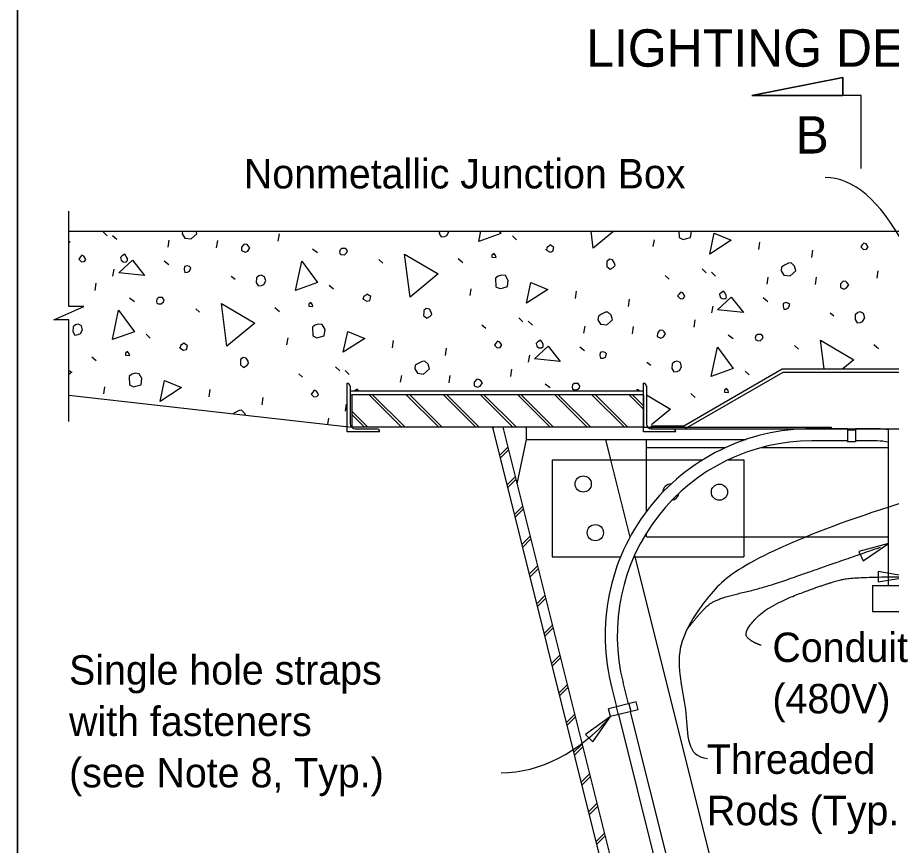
# Model space of a CAD drawing. Extents: x 0 to 30.8, y 0 to 21.2.
# Drawn here: x 0 to 4.493, y 5.377 to 9.634 of the extents above; entities that cross this region are included whole.
import ezdxf

# ---------------------------------------------------------------- set-up
doc = ezdxf.new("R2010")
doc.units = 0
for name, color, linetype in [('ActivePts-ConstElements', 7, 'Continuous'), ('Dimension', 7, 'Continuous'), ('Lighting', 7, 'Continuous'), ('Miscellaneous', 7, 'Continuous'), ('Miscellaneous1', 7, 'Continuous'), ('SteelGirder', 7, 'Continuous'), ('SteelGirder_h', 7, 'Continuous'), ('SupstrConc', 7, 'Continuous'), ('TextStructures', 7, 'Continuous')]:
    doc.layers.add(name, color=color, linetype=linetype)

msp = doc.modelspace()

# ---------------------------------------------------------------- linework, layer by layer
at = {"layer": 'ActivePts-ConstElements'}
msp.add_lwpolyline([(0, 0), (30.7879, 0), (30.7879, 19.4596), (0, 19.4596)], close=True, dxfattribs=at)
at = {"layer": 'Dimension'}
for p, q in [((3.7747, 9.2323), (4.2434, 9.3261)), ((4.2434, 9.3261), (4.2434, 9.2323)), ((4.3372, 9.2323), (3.7747, 9.2323)), ((4.3372, 8.8573), (4.3372, 9.2323))]:
    msp.add_line(p, q, dxfattribs=at)
for points in [[(4.2434, 9.2323), (4.2434, 9.3261), (3.7747, 9.2323)], [(4.4782, 6.9304), (4.3252, 6.8892), (4.3473, 6.8412)], [(4.5805, 6.7589), (4.4243, 6.7853), (4.4243, 6.7324)], [(3.0493, 6.0401), (2.92, 5.9486), (2.9574, 5.9111)]]:
    msp.add_lwpolyline(points, close=True, dxfattribs=at)
msp.add_lwpolyline([(0.2637, 7.5579), (0.2637, 8.0801), (0.1862, 8.0801), (0.2637, 8.1139), (0.3412, 8.1476), (0.2637, 8.1476), (0.2637, 8.638)], dxfattribs=at)
for centre, major_axis, ratio, start_param, end_param in [((4.1852, 6.2941), (0.0332, -2.5173), 0.313255, 2.075166, 3.141607), ((2.472, 7.3449), (-0.0144, 1.5941), 0.622544, 3.141613, 3.747853)]:
    msp.add_ellipse(centre, major_axis=major_axis, ratio=ratio, start_param=start_param, end_param=end_param, dxfattribs=at)
for points, degree in [([(4.9783, 7.2679), (4.6826, 7.1814), (4.1926, 7.0333), (3.6822, 6.8035), (3.5444, 6.6555), (3.3556, 6.3798), (3.4596, 6.0576), (3.4353, 5.8356), (3.5477, 5.8254)], 3), ([(3.4425, 6.4892), (3.5087, 6.5738), (3.5852, 6.6453), (3.8353, 6.7014), (4.0956, 6.7933), (4.4362, 6.9111)], 2), ([(3.8226, 6.4065), (3.7639, 6.427), (3.7332, 6.478), (3.8583, 6.6108), (4.1824, 6.7333), (4.3074, 6.7588), (4.5805, 6.7588)], 2), ([(2.6234, 4.9322), (4.0961, 4.9424), (5.0399, 4.9935), (5.0194, 5.4888), (4.9837, 6.4589)], 2)]:
    msp.add_open_spline(points, degree=degree, dxfattribs=at)
at = {"layer": 'Lighting'}
for p, q in [((4.2671, 7.5197), (4.0831, 7.5197)), ((4.4194, 7.5197), (4.3088, 7.5197)), ((4.2671, 7.4572), (4.0831, 7.4572)), ((4.4197, 7.4572), (4.3088, 7.4572)), ((4.3949, 6.7147), (5.0928, 6.7147)), ((4.3949, 6.7147), (4.3949, 6.5793)), ((4.6053, 6.5793), (4.3949, 6.5793)), ((3.1129, 6.2147), (3.1402, 6.1058)), ((3.0557, 6.1863), (3.0796, 6.0906)), ((3.0897, 6.0502), (3.5882, 4.0564)), ((3.1503, 6.0653), (3.6487, 4.0715))]:
    msp.add_line(p, q, dxfattribs=at)
for centre, radius, start, end in [((4.0831, 6.4572), 1.0625, 90.0002, 194.7729), ((4.4191, 7.2072), 0.3125, 79.1097, 89.9466), ((4.0831, 6.4572), 1, 90.0002, 194.0354), ((4.4191, 7.2072), 0.25, 76.3399, 89.8674)]:
    msp.add_arc(centre, radius, start, end, dxfattribs=at)
at = {"layer": 'Miscellaneous'}
for p, q in [((0.4402, 8.532), (0.4612, 8.5117)), ((0.489, 8.514), (0.51, 8.4937)), ((1.341, 8.4835), (1.3464, 8.5212)), ((2.5449, 8.511), (2.5658, 8.4907)), ((0.2637, 8.4849), (0.2707, 8.4788)), ((0.7745, 8.4533), (0.7806, 8.4886)), ((1.0238, 8.4502), (1.0292, 8.4879)), ((3.2687, 8.4565), (3.2747, 8.4917)), ((3.8111, 8.4413), (3.8165, 8.479)), ((1.5169, 8.4452), (1.5427, 8.4262)), ((4.0834, 8.4004), (4.0888, 8.4381)), ((0.7544, 8.3832), (0.7778, 8.3636)), ((1.858, 8.3891), (1.8783, 8.3712)), ((2.2655, 8.3947), (2.2888, 8.3751)), ((0.4907, 8.3048), (0.4968, 8.3401)), ((3.5192, 8.3424), (3.5402, 8.3222)), ((3.568, 8.3244), (3.589, 8.3042)), ((4.42, 8.2939), (4.4254, 8.3316)), ((0.3992, 8.2311), (0.4046, 8.2688)), ((1.099, 8.3047), (1.1187, 8.2893)), ((3.3294, 8.3071), (3.3497, 8.2892)), ((3.8535, 8.2638), (3.8595, 8.299)), ((4.1027, 8.2607), (4.1082, 8.2984)), ((1.6031, 8.2586), (1.6241, 8.2384)), ((2.3269, 8.2041), (2.333, 8.2394)), ((2.8693, 8.189), (2.8747, 8.2267)), ((0.5751, 8.1928), (0.6009, 8.1739)), ((3.1416, 8.1481), (3.1471, 8.1858)), ((3.8334, 8.1937), (3.8568, 8.1741)), ((0.9163, 8.1367), (0.9366, 8.1189)), ((1.3237, 8.1424), (1.347, 8.1227)), ((3.5697, 8.1153), (3.5758, 8.1505)), ((2.5774, 8.0901), (2.5984, 8.0698)), ((4.178, 8.1152), (4.1976, 8.0997)), ((2.3876, 8.0547), (2.4079, 8.0369)), ((2.6262, 8.0721), (2.6472, 8.0518)), ((2.9117, 8.0114), (2.9178, 8.0467)), ((3.161, 8.0083), (3.1664, 8.046)), ((3.4782, 8.0416), (3.4836, 8.0792)), ((0.6613, 8.0063), (0.6823, 7.986)), ((3.6541, 8.0033), (3.6799, 7.9843)), ((1.3851, 7.9518), (1.3912, 7.987)), ((1.9275, 7.9366), (1.9329, 7.9743)), ((2.1999, 7.8957), (2.2053, 7.9334)), ((2.8916, 7.9413), (2.915, 7.9217)), ((3.9952, 7.9472), (4.0155, 7.9293)), ((4.4026, 7.9528), (4.426, 7.9332)), ((0.3819, 7.89), (0.4053, 7.8704)), ((2.6279, 7.8629), (2.634, 7.8982)), ((1.6356, 7.8377), (1.6566, 7.8175)), ((1.6845, 7.8197), (1.7054, 7.7995)), ((2.5364, 7.7892), (2.5418, 7.8269)), ((3.2362, 7.8628), (3.2559, 7.8474)), ((3.4265, 7.5353), (3.9317, 7.827)), ((3.9317, 7.827), (8.7519, 7.827)), ((1.4458, 7.8024), (1.4661, 7.7845)), ((1.9699, 7.7591), (1.976, 7.7943)), ((2.2192, 7.756), (2.2246, 7.7937)), ((3.4307, 7.5197), (3.9359, 7.8114)), ((3.7403, 7.8167), (3.7613, 7.7965)), ((3.9359, 7.8114), (8.7519, 7.8114)), ((0.4433, 7.6994), (0.4494, 7.7347)), ((1.6949, 7.5041), (1.6949, 7.7541)), ((1.7105, 7.7384), (1.7105, 7.5457)), ((2.7123, 7.7509), (2.7381, 7.732)), ((3.2182, 7.5041), (3.2182, 7.7541)), ((3.2338, 7.7385), (3.2338, 7.5458)), ((0.9857, 7.6843), (0.9911, 7.722)), ((1.7105, 7.7148), (3.2182, 7.7148)), ((1.7105, 7.694), (1.7181, 7.694)), ((1.9746, 7.5273), (1.8079, 7.694)), ((1.9923, 7.5273), (1.8256, 7.694)), ((2.1656, 7.5273), (1.9988, 7.694)), ((2.1832, 7.5273), (2.0165, 7.694)), ((2.3565, 7.5273), (2.1898, 7.694)), ((2.3741, 7.5273), (2.2074, 7.694)), ((2.5474, 7.5273), (2.3807, 7.694)), ((2.5651, 7.5273), (2.3983, 7.694)), ((2.7383, 7.5273), (2.5716, 7.694)), ((2.756, 7.5273), (2.5893, 7.694)), ((2.9292, 7.5273), (2.7625, 7.694)), ((2.9469, 7.5273), (2.7802, 7.694)), ((3.1201, 7.5273), (2.9534, 7.694)), ((3.1378, 7.5273), (2.9711, 7.694)), ((3.2181, 7.6203), (3.1443, 7.694)), ((3.2181, 7.6379), (3.162, 7.694)), ((3.4609, 7.7004), (3.4842, 7.6808)), ((1.2581, 7.6434), (1.2635, 7.6811)), ((1.6862, 7.6106), (1.6922, 7.6458)), ((1.8014, 7.5273), (1.7181, 7.6106)), ((1.5953, 7.5413), (1.6001, 7.5745)), ((1.7837, 7.5273), (1.7181, 7.5929)), ((1.8615, 7.5041), (1.6949, 7.5041)), ((1.7365, 7.5197), (1.8459, 7.5197)), ((2.4428, 7.5212), (2.4489, 7.5273)), ((3.3848, 7.5041), (3.2182, 7.5041)), ((3.2598, 7.5353), (3.4265, 7.5353)), ((3.2598, 7.5197), (3.2598, 7.5353)), ((3.2598, 7.5197), (3.3692, 7.5197)), ((3.2598, 7.5197), (8.7519, 7.5197)), ((2.4774, 7.3826), (2.5204, 7.4255)), ((2.481, 7.3684), (2.5239, 7.4114)), ((2.5156, 7.2298), (2.5586, 7.2728)), ((2.5192, 7.2157), (2.5621, 7.2587)), ((2.5538, 7.0771), (2.5968, 7.1201)), ((2.5573, 7.063), (2.6003, 7.1059)), ((2.592, 6.9244), (2.6349, 6.9673)), ((2.5955, 6.9102), (2.6385, 6.9532)), ((2.6302, 6.7716), (2.6731, 6.8146)), ((2.6337, 6.7575), (2.6767, 6.8005)), ((2.6684, 6.6189), (2.7113, 6.6619)), ((2.6719, 6.6048), (2.7148, 6.6477)), ((2.7065, 6.4662), (2.7495, 6.5091)), ((2.7101, 6.452), (2.753, 6.495)), ((2.7447, 6.3134), (2.7877, 6.3564)), ((2.7483, 6.2993), (2.7912, 6.3423)), ((2.7829, 6.1607), (2.8259, 6.2037)), ((2.7864, 6.1466), (2.8294, 6.1895)), ((2.8211, 6.008), (2.864, 6.0509)), ((2.8246, 5.9938), (2.8676, 6.0368)), ((2.8593, 5.8552), (2.9022, 5.8982)), ((2.8628, 5.8411), (2.9058, 5.884)), ((2.8975, 5.7025), (2.9404, 5.7455)), ((2.901, 5.6884), (2.944, 5.7313)), ((2.9356, 5.5498), (2.9786, 5.5927)), ((2.9392, 5.5356), (2.9821, 5.5786)), ((2.9738, 5.397), (3.0168, 5.44)), ((2.9774, 5.3829), (3.0203, 5.4258))]:
    msp.add_line(p, q, dxfattribs=at)
for points in [[(0.8467, 8.5218), (0.8604, 8.4996), (0.8926, 8.4953), (0.9219, 8.5213), (0.9181, 8.5353)], [(0.8486, 8.5353), (0.8467, 8.5218)], [(2.1693, 8.5353), (2.1687, 8.5241), (2.1787, 8.506), (2.1962, 8.5082), (2.2077, 8.5138), (2.2183, 8.5322), (2.2174, 8.5353)], [(2.3713, 8.4826), (2.3825, 8.5353)], [(2.4758, 8.5353), (2.4846, 8.5233), (2.3713, 8.4826)], [(2.9601, 8.4488), (2.9491, 8.5353)], [(3.065, 8.5353), (2.9601, 8.4488)], [(3.4003, 8.5353), (3.4013, 8.5024), (3.4221, 8.4924), (3.4342, 8.4956), (3.4607, 8.5027), (3.465, 8.535), (3.4648, 8.5353)], [(3.5586, 8.4177), (3.5816, 8.5248), (3.669, 8.4887), (3.5586, 8.4177)], [(1.1523, 8.4536), (1.152, 8.4354), (1.1697, 8.4272), (1.1835, 8.4335), (1.1948, 8.4495), (1.1867, 8.4602), (1.18, 8.4662), (1.169, 8.4684), (1.1642, 8.4671), (1.1523, 8.4536)], [(2.7195, 8.4387), (2.7379, 8.4281), (2.7524, 8.432), (2.7575, 8.4515), (2.7385, 8.4645), (2.7301, 8.4571), (2.7211, 8.4521), (2.7195, 8.4387), (2.7182, 8.4436)], [(4.3354, 8.455), (4.3496, 8.4407), (4.3647, 8.4422), (4.3724, 8.452), (4.3711, 8.4568), (4.3624, 8.47), (4.3508, 8.4747), (4.3431, 8.4648), (4.3354, 8.455)], [(0.3146, 8.3922), (0.3288, 8.3779), (0.3439, 8.3794), (0.3517, 8.3892), (0.3504, 8.394), (0.3417, 8.4072), (0.3301, 8.4119), (0.3223, 8.402), (0.3146, 8.3922)], [(0.5336, 8.3862), (0.5435, 8.3785), (0.5568, 8.3769), (0.5652, 8.3843), (0.565, 8.3946), (0.5594, 8.406), (0.5513, 8.4168), (0.5381, 8.4081), (0.5298, 8.4007), (0.5336, 8.3862)], [(1.6586, 8.4185), (1.6648, 8.4149), (1.6805, 8.414), (1.6931, 8.4251), (1.696, 8.4336), (1.6873, 8.4468), (1.6666, 8.4465), (1.6583, 8.4391), (1.656, 8.4281), (1.6586, 8.4185)], [(2.0183, 8.1965), (1.9904, 8.4168), (2.1625, 8.3154), (2.0183, 8.1965)], [(2.4394, 8.4025), (2.4606, 8.4004), (2.458, 8.4101), (2.45, 8.4209), (2.4392, 8.4128), (2.4394, 8.4025)], [(0.5202, 8.3205), (0.5907, 8.3859), (0.6532, 8.3069), (0.5202, 8.3205)], [(0.8571, 8.3383), (0.861, 8.3238), (0.8737, 8.3246), (0.8851, 8.3303), (0.8909, 8.3473), (0.8841, 8.3533), (0.8725, 8.3579), (0.858, 8.3541), (0.8571, 8.3383)], [(1.4295, 8.2303), (1.4616, 8.3812), (1.5429, 8.271), (1.4295, 8.2303)], [(3.0299, 8.3718), (3.0296, 8.3536), (3.0462, 8.3399), (3.0618, 8.3493), (3.072, 8.3598), (3.0687, 8.3718), (3.0594, 8.3874), (3.043, 8.3908), (3.0304, 8.3797), (3.0299, 8.3718)], [(3.9257, 8.3323), (3.9394, 8.3101), (3.9716, 8.3058), (4.0009, 8.3317), (3.9944, 8.3559), (3.9772, 8.372), (3.9644, 8.3711), (3.944, 8.3605), (3.9284, 8.3511), (3.9257, 8.3323)], [(1.2283, 8.2954), (1.2269, 8.2717), (1.2369, 8.2537), (1.2545, 8.2558), (1.2659, 8.2615), (1.2765, 8.2798), (1.2707, 8.3016), (1.2529, 8.3098), (1.2409, 8.3065), (1.2283, 8.2954)], [(2.4582, 8.2936), (2.4595, 8.25), (2.4803, 8.24), (2.4924, 8.2433), (2.5189, 8.2504), (2.5232, 8.2826), (2.5089, 8.3072), (2.49, 8.3099), (2.4707, 8.3048), (2.4582, 8.2936)], [(2.6168, 8.1653), (2.6399, 8.2724), (2.7272, 8.2363), (2.6168, 8.1653)], [(4.2313, 8.264), (4.231, 8.2458), (4.2487, 8.2377), (4.2625, 8.244), (4.2738, 8.2599), (4.2657, 8.2707), (4.2589, 8.2766), (4.248, 8.2789), (4.2432, 8.2776), (4.2313, 8.264)], [(3.6126, 8.1966), (3.6225, 8.1889), (3.6358, 8.1873), (3.6442, 8.1947), (3.644, 8.205), (3.6384, 8.2165), (3.6303, 8.2273), (3.6171, 8.2185), (3.6087, 8.2111), (3.6126, 8.1966)], [(0.7168, 8.1661), (0.723, 8.1626), (0.7388, 8.1616), (0.7513, 8.1728), (0.7542, 8.1813), (0.7455, 8.1945), (0.7249, 8.1941), (0.7165, 8.1867), (0.7143, 8.1758), (0.7168, 8.1661)], [(1.7778, 8.1864), (1.7961, 8.1758), (1.8106, 8.1797), (1.8157, 8.1992), (1.7967, 8.2122), (1.7884, 8.2048), (1.7793, 8.1998), (1.7778, 8.1864), (1.7765, 8.1912)], [(3.3936, 8.2027), (3.4078, 8.1883), (3.4229, 8.1898), (3.4306, 8.1996), (3.4293, 8.2045), (3.4206, 8.2177), (3.409, 8.2223), (3.4013, 8.2125), (3.3936, 8.2027)], [(3.5992, 8.1309), (3.6696, 8.1964), (3.7322, 8.1174), (3.5992, 8.1309)], [(1.0766, 7.9441), (1.0486, 8.1644), (1.2207, 8.063), (1.0766, 7.9441)], [(1.4976, 8.1501), (1.5188, 8.1481), (1.5163, 8.1577), (1.5082, 8.1685), (1.4974, 8.1604), (1.4976, 8.1501)], [(2.0882, 8.1194), (2.0879, 8.1012), (2.1045, 8.0876), (2.1201, 8.0969), (2.1302, 8.1074), (2.127, 8.1195), (2.1176, 8.1351), (2.1012, 8.1385), (2.0886, 8.1273), (2.0882, 8.1194)], [(3.936, 8.1487), (3.9399, 8.1342), (3.9526, 8.135), (3.9641, 8.1407), (3.9699, 8.1578), (3.9631, 8.1637), (3.9515, 8.1684), (3.937, 8.1645), (3.936, 8.1487)], [(0.4878, 7.9779), (0.5198, 8.1288), (0.6011, 8.0186), (0.4878, 7.9779)], [(2.9839, 8.0799), (2.9976, 8.0577), (3.0298, 8.0534), (3.0591, 8.0794), (3.0526, 8.1035), (3.0354, 8.1196), (3.0227, 8.1188), (3.0022, 8.1081), (2.9866, 8.0988), (2.9839, 8.0799)], [(4.3073, 8.1058), (4.3059, 8.0822), (4.3159, 8.0641), (4.3334, 8.0662), (4.3449, 8.0719), (4.3555, 8.0903), (4.3496, 8.112), (4.3319, 8.1202), (4.3198, 8.117), (4.3073, 8.1058)], [(0.2865, 8.043), (0.2851, 8.0194), (0.2951, 8.0013), (0.3127, 8.0035), (0.3241, 8.0091), (0.3347, 8.0275), (0.3289, 8.0492), (0.3112, 8.0574), (0.2991, 8.0542), (0.2865, 8.043)], [(1.5164, 8.0413), (1.5177, 7.9977), (1.5385, 7.9877), (1.5506, 7.9909), (1.5772, 7.998), (1.5815, 8.0303), (1.5671, 8.0549), (1.5483, 8.0576), (1.5289, 8.0524), (1.5164, 8.0413)], [(1.675, 7.913), (1.6981, 8.0201), (1.7854, 7.984), (1.675, 7.913)], [(3.2895, 8.0117), (3.2892, 7.9935), (3.3069, 7.9853), (3.3207, 7.9916), (3.332, 8.0076), (3.3239, 8.0183), (3.3172, 8.0243), (3.3062, 8.0265), (3.3014, 8.0252), (3.2895, 8.0117)], [(3.7958, 7.9765), (3.8019, 7.973), (3.8177, 7.9721), (3.8303, 7.9832), (3.8332, 7.9917), (3.8245, 8.0049), (3.8038, 8.0046), (3.7955, 7.9972), (3.7932, 7.9862), (3.7958, 7.9765)], [(0.836, 7.934), (0.8543, 7.9234), (0.8688, 7.9273), (0.874, 7.9468), (0.8549, 7.9598), (0.8466, 7.9524), (0.8376, 7.9474), (0.836, 7.934), (0.8347, 7.9389)], [(2.4518, 7.9503), (2.466, 7.936), (2.4811, 7.9375), (2.4889, 7.9473), (2.4876, 7.9521), (2.4789, 7.9653), (2.4673, 7.97), (2.4595, 7.9601), (2.4518, 7.9503)], [(2.6708, 7.9443), (2.6807, 7.9366), (2.694, 7.935), (2.7024, 7.9424), (2.7022, 7.9527), (2.6966, 7.9641), (2.6885, 7.9749), (2.6753, 7.9662), (2.667, 7.9588), (2.6708, 7.9443)], [(4.1463, 7.827), (4.1276, 7.9749), (4.2997, 7.8734), (4.2434, 7.827)], [(0.5558, 7.8978), (0.5771, 7.8957), (0.5745, 7.9054), (0.5664, 7.9162), (0.5556, 7.9081), (0.5558, 7.8978)], [(2.6574, 7.8786), (2.7279, 7.944), (2.7904, 7.865), (2.6574, 7.8786)], [(2.9943, 7.8964), (2.9981, 7.8819), (3.0109, 7.8827), (3.0223, 7.8883), (3.0281, 7.9054), (3.0213, 7.9114), (3.0097, 7.916), (2.9952, 7.9121), (2.9943, 7.8964)], [(3.5667, 7.7883), (3.5988, 7.9393), (3.6801, 7.8291), (3.5667, 7.7883)], [(1.1464, 7.8671), (1.1461, 7.8489), (1.1627, 7.8352), (1.1783, 7.8446), (1.1884, 7.8551), (1.1852, 7.8671), (1.1758, 7.8827), (1.1594, 7.8861), (1.1469, 7.875), (1.1464, 7.8671)], [(2.0421, 7.8276), (2.0558, 7.8054), (2.0881, 7.8011), (2.1173, 7.827), (2.1109, 7.8512), (2.0936, 7.8673), (2.0809, 7.8664), (2.0604, 7.8558), (2.0448, 7.8464), (2.0421, 7.8276)], [(3.3655, 7.8535), (3.3641, 7.8298), (3.3741, 7.8118), (3.3916, 7.8139), (3.4031, 7.8195), (3.4137, 7.8379), (3.4079, 7.8597), (3.3901, 7.8678), (3.3781, 7.8646), (3.3655, 7.8535)], [(0.2637, 7.8196), (0.2789, 7.8107), (0.2637, 7.7981)], [(0.5746, 7.7889), (0.576, 7.7453), (0.5967, 7.7353), (0.6088, 7.7386), (0.6354, 7.7457), (0.6397, 7.7779), (0.6253, 7.8025), (0.6065, 7.8053), (0.5872, 7.8001), (0.5746, 7.7889)], [(2.3477, 7.7593), (2.3474, 7.7411), (2.3651, 7.733), (2.379, 7.7393), (2.3902, 7.7552), (2.3822, 7.766), (2.3754, 7.7719), (2.3644, 7.7742), (2.3596, 7.7729), (2.3477, 7.7593)], [(0.7332, 7.6606), (0.7563, 7.7677), (0.8436, 7.7316), (0.7332, 7.6606)], [(2.854, 7.7242), (2.8602, 7.7207), (2.876, 7.7197), (2.8885, 7.7308), (2.8914, 7.7394), (2.8827, 7.7526), (2.8621, 7.7522), (2.8537, 7.7448), (2.8515, 7.7339), (2.854, 7.7242)], [(1.51, 7.698), (1.5242, 7.6836), (1.5394, 7.6851), (1.5471, 7.6949), (1.5458, 7.6998), (1.5371, 7.713), (1.5255, 7.7176), (1.5178, 7.7078), (1.51, 7.698)], [(1.7525, 7.7148), (1.7467, 7.7226), (1.735, 7.7148)], [(3.1868, 7.7148), (3.1858, 7.7225), (3.1989, 7.7148)], [(3.2338, 7.6942), (3.3579, 7.6211), (3.2589, 7.5394)], [(3.6348, 7.7082), (3.656, 7.7062), (3.6535, 7.7158), (3.6454, 7.7266), (3.6346, 7.7185), (3.6348, 7.7082)], [(1.1716, 7.5894), (1.1691, 7.5988), (1.1518, 7.6149), (1.1391, 7.6141), (1.1187, 7.6034), (1.1074, 7.5967)]]:
    msp.add_lwpolyline(points, dxfattribs=at)
for centre, radius, start, end in [((1.6949, 7.7384), 0.0156, 359.9953, 89.9953), ((3.2182, 7.7385), 0.0156, 359.9953, 89.9953), ((1.7365, 7.5457), 0.026, 179.9953, 269.9953), ((1.8459, 7.5041), 0.0156, 359.9953, 89.9953), ((3.2598, 7.5458), 0.026, 179.9953, 269.9953), ((3.3692, 7.5041), 0.0156, 359.9953, 89.9953)]:
    msp.add_arc(centre, radius, start, end, dxfattribs=at)
at = {"layer": 'Miscellaneous1'}
msp.add_lwpolyline([(0, 19.8), (30.8, 19.8), (30.8, 0), (0, 0)], close=True, dxfattribs=at)
at = {"layer": 'SteelGirder'}
for p, q in [((1.7181, 7.694), (1.7181, 7.5273)), ((3.2181, 7.694), (1.7181, 7.694)), ((3.2181, 7.694), (3.2181, 7.5272)), ((3.2181, 7.5273), (1.7181, 7.5273)), ((2.4413, 7.5273), (4.0037, 1.2773)), ((2.495, 7.5273), (4.0574, 1.2773)), ((2.6168, 7.4647), (2.6168, 7.5273)), ((3.2155, 7.5272), (3.2182, 7.5299)), ((3.2155, 7.5272), (3.2182, 7.5299)), ((3.2181, 7.5272), (4.1827, 7.5272)), ((4.1827, 7.5272), (4.1827, 7.5197)), ((4.2671, 7.5197), (4.2671, 7.452)), ((4.2671, 7.5197), (4.3088, 7.5197)), ((4.2671, 7.5145), (4.3088, 7.5145)), ((4.3088, 7.5197), (4.3088, 7.452)), ((4.4782, 6.7147), (4.4782, 7.5197)), ((2.6147, 7.4647), (2.5676, 7.2369)), ((2.6168, 7.4647), (3.7457, 7.4647)), ((3.0228, 7.4647), (3.0489, 7.3606)), ((3.2338, 7.3502), (3.2338, 7.4647)), ((3.2338, 7.4231), (3.6403, 7.4231)), ((3.824, 7.4231), (4.4782, 7.4231)), ((4.3088, 7.452), (4.2671, 7.452)), ((2.7494, 7.3606), (2.7494, 6.8606)), ((2.7494, 7.3606), (3.5237, 7.3606)), ((3.6542, 7.3606), (3.7338, 7.3606)), ((3.7338, 7.3606), (3.7338, 6.8606)), ((3.7338, 6.9647), (4.4782, 6.9647)), ((2.7494, 6.8606), (3.1001, 6.8606)), ((3.168, 6.8606), (3.7338, 6.8606)), ((3.1739, 6.8606), (4.161, 2.9127)), ((3.1806, 6.1159), (3.0392, 6.0805)), ((3.1908, 6.0754), (3.1806, 6.1159)), ((3.0493, 6.0401), (3.0392, 6.0805)), ((3.1908, 6.0754), (3.0493, 6.0401)), ((3.0774, 6.0901), (3.0875, 6.0496)), ((3.1424, 6.1063), (3.1525, 6.0659))]:
    msp.add_line(p, q, dxfattribs=at)
for centre in [(2.9084, 7.2356), (3.6088, 7.1939), (2.9709, 6.9856)]:
    msp.add_circle(centre, 0.0417, dxfattribs=at)
for start, end in [(88.5209, 180.5137), (277.7816, 351.253)]:
    msp.add_arc((3.3588, 7.1939), 0.0417, start, end, dxfattribs=at)
at = {"layer": 'SteelGirder_h'}
for p, q in [((3.2338, 7.0956), (3.2338, 7.4231)), ((3.0489, 7.3606), (3.1484, 6.9625)), ((3.2338, 6.9647), (3.2338, 6.9851)), ((3.2338, 6.9647), (3.7338, 6.9647)), ((3.1718, 6.869), (3.1739, 6.8606))]:
    msp.add_line(p, q, dxfattribs=at)
at = {"layer": 'SupstrConc'}
for p, q in [((0.2637, 8.5353), (8.7519, 8.5353)), ((0.2637, 7.6925), (1.7181, 7.5273))]:
    msp.add_line(p, q, dxfattribs=at)

# ---------------------------------------------------------------- texts
at = {"layer": 'Dimension'}
for s, p in [('Conduit', (3.8811, 6.3208)), ('Single hole straps', (0.2652, 6.2044)), ('(480V)', (3.8811, 6.0568)), ('with fasteners', (0.2652, 5.9404)), ('Threaded', (3.5444, 5.7456)), ('(see Note 8, Typ.)', (0.2652, 5.6764)), ('Rods (Typ.)', (3.5444, 5.4816))]:
    msp.add_text(s, height=0.1512, dxfattribs=at).set_placement(p)
at = {"layer": 'TextStructures'}
for s, height, p in [('LIGHTING DETAILS FOR CONCRETE BOX GIRDER BRIDGE', 0.192, (2.9236, 9.3811)), ('B', 0.192, (3.9998, 8.9346)), ('Nonmetallic Junction Box', 0.1512, (1.1641, 8.7552))]:
    msp.add_text(s, height=height, dxfattribs=at).set_placement(p)

doc.saveas('drawing.dxf')
